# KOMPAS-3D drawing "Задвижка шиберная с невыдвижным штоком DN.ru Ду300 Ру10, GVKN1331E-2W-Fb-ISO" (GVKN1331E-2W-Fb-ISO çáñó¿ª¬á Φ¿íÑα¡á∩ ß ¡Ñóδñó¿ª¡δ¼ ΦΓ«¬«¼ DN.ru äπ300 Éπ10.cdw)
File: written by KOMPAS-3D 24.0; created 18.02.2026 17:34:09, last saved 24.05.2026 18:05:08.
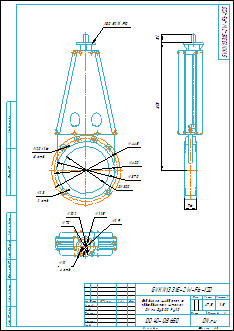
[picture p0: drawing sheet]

Document properties: Автор: R2D2; Форматы листов документа: A3; Полное имя файла: GVKN1331E-2W-Fb-ISO Задвижка шиберная с невыдвижным штоком DN.ru Ду300 Ру10.m3d; Масса: 47.5; Наименование: Задвижка шиберная с невыдвижным штоком DN.ru Ду300 Ру10; Количество листов документа: 1; Примечание: D040-08650

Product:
- Part/product: Задвижка шиберная с невыдвижным штоком DN.ru Ду300 Ру10  | designation GVKN1331E-2W-Fb-ISO
    Масса: 47.5
    Раздел спецификации: Прочие изделия
    Примечание: D040-08650

Views: Вид 1, Спереди, Проекционный вид 2
Referenced files in E:\Работа\Зайцев\GVKN1331E-2W-Fb-ISO Задвижка шиберная с невидвижным штоком DN.ru Ду300 Ру10\: GVKN1331E-2W-Fb-ISO Задвижка шиберная с невыдвижным штоком DN.ru Ду300 Ру10.m3d
Referenced files in E:\Работа\Зайцев\Для компаса\: чертеж DN.ru А3.cdt
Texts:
  ISO 5211 F10
  GVKN1331E-2W-Fb-ISO
  чертеж DN.ru А3.cdt
  Задвижка шиберная с
  невыдвижным штоком
  DN.ru Ду300 Ру10
  Задвижка шиберная с невыдвижным штоком DN.ru Ду300 Ру10
  GVKN1331E-2W-Fb-ISO Задвижка шиберная с невыдвижным штоком DN.ru Ду300 Ру10
Dimensions and other numbers on the sheet: 0; 3; 2; 4; 20; 8 отв.; 23; 2 отв.; 445; 370; 300; 400; 76; 815; 51; 1:5; 1; 47,5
